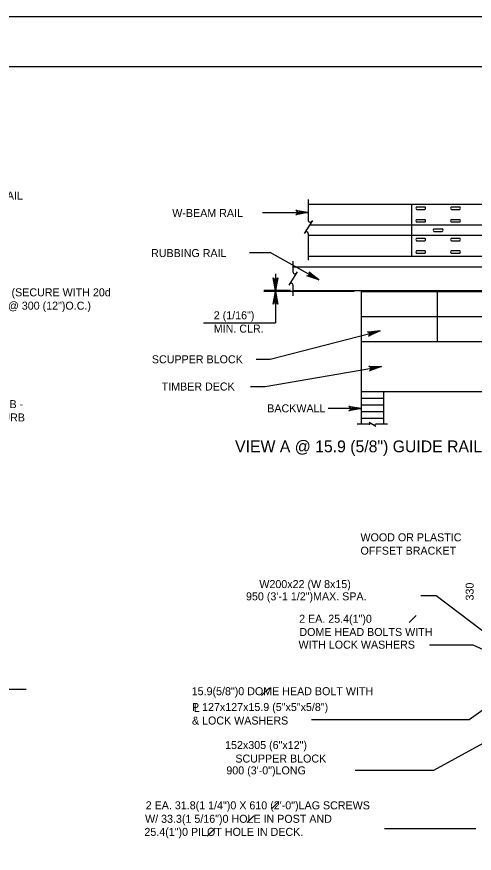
# Model space of a CAD drawing. Extents: x 0 to 36.3, y -66 to 0.
# Drawn here: x 20.36 to 27.22, y -12.54 to 0 of the extents above; entities that cross this region are included whole.
import ezdxf

# ---------------------------------------------------------------- set-up
doc = ezdxf.new("R2010")
doc.units = 0
for name, color, linetype in [('1', 7, 'Continuous'), ('2', 7, 'Continuous'), ('3', 7, 'Continuous'), ('52', 7, 'Continuous'), ('63', 7, 'Continuous')]:
    doc.layers.add(name, color=color, linetype=linetype)

msp = doc.modelspace()

# ---------------------------------------------------------------- linework, layer by layer
at = {"layer": '1'}
msp.add_lwpolyline([(1.75, -21.25), (33.25, -21.25), (33.25, -0.75), (1.75, -0.75)], close=True, dxfattribs=at)
at = {"layer": '2'}
for p, q in [((24.733, -2.741), (24.733, -3.053)), ((24.733, -2.808), (26.285, -2.808)), ((26.285, -2.808), (26.285, -3.589)), ((26.285, -2.808), (28.129, -2.808)), ((26.359, -2.851), (26.484, -2.851)), ((26.881, -2.851), (27.006, -2.851)), ((26.359, -2.89), (26.484, -2.89)), ((26.881, -2.89), (27.006, -2.89)), ((24.795, -3.055), (24.672, -3.251)), ((24.754, -3.12), (27.667, -3.12)), ((26.359, -3.038), (26.484, -3.038)), ((26.359, -3.077), (26.484, -3.077)), ((26.881, -3.038), (27.006, -3.038)), ((26.881, -3.077), (27.006, -3.077)), ((24.733, -3.25), (24.733, -3.648)), ((26.619, -3.179), (26.744, -3.179)), ((26.619, -3.218), (26.744, -3.218)), ((24.733, -3.276), (27.667, -3.276)), ((26.359, -3.319), (26.484, -3.319)), ((26.359, -3.358), (26.484, -3.358)), ((26.881, -3.319), (27.006, -3.319)), ((26.881, -3.358), (27.006, -3.358)), ((26.359, -3.507), (26.484, -3.507)), ((26.881, -3.507), (27.006, -3.507)), ((24.733, -3.589), (28.129, -3.589)), ((26.359, -3.546), (26.484, -3.546)), ((26.881, -3.546), (27.006, -3.546)), ((24.504, -3.663), (24.504, -3.825)), ((24.504, -3.75), (28.459, -3.75)), ((24.566, -3.827), (24.443, -4.023)), ((24.504, -4.022), (24.504, -4.186)), ((24.504, -4.104), (28.93, -4.104)), ((25.529, -4.12), (30.679, -4.12)), ((25.529, -4.12), (25.529, -6.109)), ((26.668, -4.12), (26.668, -4.87)), ((26.777, -4.12), (30.459, -4.12)), ((25.529, -4.495), (30.679, -4.495)), ((25.529, -4.87), (30.679, -4.87)), ((25.529, -5.62), (30.679, -5.62)), ((25.864, -5.62), (25.864, -6.109)), ((25.529, -5.72), (25.864, -5.72)), ((25.529, -5.82), (25.864, -5.82)), ((25.529, -5.92), (25.864, -5.92)), ((25.529, -6.02), (25.864, -6.02)), ((25.648, -6.079), (25.746, -6.14))]:
    msp.add_line(p, q, dxfattribs=at)
for centre, radius, start, end in [((26.371, -2.87), 0.0228, 120.8559, 239.1441), ((26.472, -2.87), 0.0228, 300.8559, 59.1441), ((26.893, -2.87), 0.0228, 120.8559, 239.1441), ((26.994, -2.87), 0.0228, 300.8559, 59.1441), ((24.762, -3.053), 0.0289, 180, 330), ((26.371, -3.058), 0.0228, 120.8559, 239.1441), ((26.472, -3.058), 0.0228, 300.8559, 59.1441), ((26.893, -3.058), 0.0228, 120.8559, 239.1441), ((26.994, -3.058), 0.0228, 300.8559, 59.1441), ((24.705, -3.253), 0.0289, 5.3286, 147.8672), ((26.631, -3.198), 0.0228, 120.8559, 239.1441), ((26.733, -3.198), 0.0228, 300.8559, 59.1441), ((26.371, -3.339), 0.0228, 120.8559, 239.1441), ((26.472, -3.339), 0.0228, 300.8559, 59.1441), ((26.893, -3.339), 0.0228, 120.8559, 239.1441), ((26.994, -3.339), 0.0228, 300.8559, 59.1441), ((26.371, -3.526), 0.0228, 120.8559, 239.1441), ((26.472, -3.526), 0.0228, 300.8559, 59.1441), ((26.893, -3.526), 0.0228, 120.8559, 239.1441), ((26.994, -3.526), 0.0228, 300.8559, 59.1441), ((24.533, -3.825), 0.0289, 180, 330), ((24.476, -4.025), 0.0289, 5.3286, 147.8672), ((25.647, -6.095), 0.0144, 270, 60), ((25.747, -6.124), 0.0144, 95.3286, 237.8672)]:
    msp.add_arc(centre, radius, start, end, dxfattribs=at)
at = {"layer": '3'}
for p, q in [((24.046, -2.937), (24.733, -2.937)), ((23.849, -3.537), (24.164, -3.537)), ((24.893, -3.945), (24.164, -3.537)), ((24.242, -3.854), (24.242, -4.587)), ((24.467, -4.104), (24.068, -4.104)), ((25.423, -4.12), (24.068, -4.12)), ((23.16, -4.587), (24.242, -4.587)), ((24.164, -5.136), (25.81, -4.71)), ((23.951, -5.136), (24.164, -5.136)), ((24.085, -5.542), (25.83, -5.245)), ((23.868, -5.542), (24.085, -5.542)), ((25.647, -6.109), (25.465, -6.109)), ((25.921, -6.109), (25.746, -6.109)), ((26.655, -8.682), (26.424, -8.682)), ((27.626, -9.419), (26.655, -8.682)), ((26.246, -9.084), (26.351, -8.979)), ((27.206, -9.42), (26.554, -9.42)), ((28.12, -9.832), (27.206, -9.42)), ((18.789, -10.081), (20.5, -10.081)), ((24.032, -10.178), (24.151, -10.059)), ((27.563, -10.245), (27.149, -10.541)), ((28.383, -10.334), (26.613, -11.299)), ((27.149, -10.541), (24.783, -10.541)), ((26.613, -11.299), (25.437, -11.299)), ((24.189, -11.871), (24.293, -11.767)), ((23.817, -12.079), (23.917, -11.979)), ((23.215, -12.287), (23.336, -12.165)), ((27.246, -12.173), (25.877, -12.173))]:
    msp.add_line(p, q, dxfattribs=at)
for points in [[(24.733, -2.937), (24.547, -2.972), (24.561, -2.962), (24.569, -2.95), (24.571, -2.937), (24.569, -2.925), (24.561, -2.912), (24.547, -2.902), (24.733, -2.937), (24.561, -2.912), (24.569, -2.925), (24.733, -2.937), (24.571, -2.937), (24.569, -2.95), (24.733, -2.937), (24.561, -2.962)], [(24.893, -3.945), (24.714, -3.884), (24.731, -3.882), (24.744, -3.875), (24.752, -3.865), (24.756, -3.853), (24.755, -3.839), (24.748, -3.823), (24.893, -3.945), (24.755, -3.839), (24.756, -3.853), (24.893, -3.945), (24.752, -3.865), (24.744, -3.875), (24.893, -3.945), (24.731, -3.882)], [(24.242, -4.104), (24.207, -3.917), (24.217, -3.932), (24.229, -3.939), (24.242, -3.941), (24.254, -3.939), (24.267, -3.932), (24.277, -3.917), (24.242, -4.104), (24.267, -3.932), (24.254, -3.939), (24.242, -4.104), (24.242, -3.941), (24.229, -3.939), (24.242, -4.104), (24.217, -3.932)], [(24.242, -4.12), (24.277, -4.307), (24.267, -4.292), (24.254, -4.285), (24.242, -4.283), (24.229, -4.285), (24.217, -4.292), (24.207, -4.307), (24.242, -4.12), (24.217, -4.292), (24.229, -4.285), (24.242, -4.12), (24.242, -4.283), (24.254, -4.285), (24.242, -4.12), (24.267, -4.292)], [(25.81, -4.71), (25.638, -4.791), (25.65, -4.778), (25.654, -4.764), (25.653, -4.751), (25.647, -4.739), (25.637, -4.729), (25.621, -4.723), (25.81, -4.71), (25.637, -4.729), (25.647, -4.739), (25.81, -4.71), (25.653, -4.751), (25.654, -4.764), (25.81, -4.71), (25.65, -4.778)], [(25.83, -5.244), (25.652, -5.31), (25.665, -5.298), (25.67, -5.284), (25.67, -5.272), (25.666, -5.26), (25.656, -5.249), (25.64, -5.241), (25.83, -5.244), (25.656, -5.249), (25.666, -5.26), (25.83, -5.244), (25.67, -5.272), (25.67, -5.284), (25.83, -5.244), (25.665, -5.298)]]:
    msp.add_lwpolyline(points, dxfattribs=at)
at = {"layer": '52'}
for points in [[(25.53, -5.876), (25.034, -5.876)], [(25.53, -5.876), (25.344, -5.911), (25.358, -5.901), (25.366, -5.888), (25.368, -5.876), (25.366, -5.863), (25.358, -5.851), (25.344, -5.841), (25.53, -5.876), (25.358, -5.851), (25.366, -5.863), (25.53, -5.876), (25.368, -5.876), (25.366, -5.888), (25.53, -5.876), (25.358, -5.901)]]:
    msp.add_lwpolyline(points, dxfattribs=at)
at = {"layer": '63'}
msp.add_lwpolyline([(0, -22), (34, -22), (34, 0), (0, 0)], close=True, dxfattribs=at)

# ---------------------------------------------------------------- texts
at = {"layer": '2'}
msp.add_text('VIEW A @ 15.9 (5/8") GUIDE RAIL CONNECTION PLATE', height=0.17717, dxfattribs=at).set_placement((23.635, -6.53))
at = {"layer": '3'}
for s, p in [('152x305 (6"x12") RAIL', (18.82, -2.742)), ('W-BEAM RAIL', (22.692, -3.003)), ('RUBBING RAIL', (22.374, -3.603)), ('RETAINER BLOCK, (SECURE WITH 20d', (18.791, -4.192)), ('THREADED NAILS @ 300 (12")O.C.)', (18.791, -4.392)), ('2 (1/16")', (23.315, -4.536)), ('MIN. CLR.', (23.315, -4.736)), ('SCUPPER BLOCK', (22.386, -5.196)), ('TIMBER DECK', (22.533, -5.604)), ('(RECESS FLUSH WITH CURB -', (18.119, -5.868)), ('BACKWALL', (24.118, -5.931)), ('USE WITH OR WITHOUT CURB', (18.119, -6.068)), ('WOOD OR PLASTIC', (25.517, -7.865)), ('OFFSET BRACKET', (25.517, -8.065)), ('W200x22 (W 8x15)', (23.999, -8.566)), ('950 (3\'-1 1/2")MAX. SPA.', (23.799, -8.75)), ('2 EA. 25.4(1")0', (24.596, -9.086)), ('DOME HEAD BOLTS WITH', (24.6, -9.284)), ('WITH LOCK WASHERS', (24.587, -9.474)), ('15.9(5/8")0 DOME HEAD BOLT WITH', (22.984, -10.172)), ('P 127x127x15.9 (5"x5"x5/8")', (22.988, -10.409)), ('L', (23.014, -10.423)), ('& LOCK WASHERS', (22.988, -10.612)), ('152x305 (6"x12")', (23.485, -10.979)), ('SCUPPER BLOCK', (23.639, -11.182)), ('900 (3\'-0")LONG', (23.504, -11.359)), ('2 EA. 31.8(1 1/4")0 X 610 (2\'-0")LAG SCREWS', (22.294, -11.883)), ('W/ 33.3(1 5/16")0 HOLE IN POST AND', (22.284, -12.085)), ('25.4(1")0 PILOT HOLE IN DECK.', (22.274, -12.281))]:
    msp.add_text(s, height=0.12, dxfattribs=at).set_placement(p)
msp.add_text('330', height=0.12, rotation=90, dxfattribs=at).set_placement((27.215, -8.752))

doc.saveas('drawing.dxf')
